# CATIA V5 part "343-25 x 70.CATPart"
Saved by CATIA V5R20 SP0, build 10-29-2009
Part number: 343-25 x 70
Definition: NONE
Nomenclature: 343-25 x 70
Source: Unknown
Description: 343-25 x 70
Bounding box of the stored display mesh (mm): x 0 to 70, y -18 to 18, z -18 to 18
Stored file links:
  C:\Users\Utente\Desktop\IO LAVORO\3D X SITO CF\X SITO\343-348\343-25 x 70.CATPart
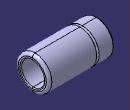
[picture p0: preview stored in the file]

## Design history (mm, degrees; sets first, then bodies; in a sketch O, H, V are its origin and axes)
Body1 "343-25 x 70" (main body)
  Solid1: solid without history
